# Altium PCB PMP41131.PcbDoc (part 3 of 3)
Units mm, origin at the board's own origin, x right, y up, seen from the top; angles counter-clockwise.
Board outline 53.98 x 39 mm, 6 copper layers (Top Layer, Signal Layer 1, Signal Layer 2, Signal Layer 3, Signal Layer 4, Bottom Layer), stack 1.835 mm thick; 91 components, 60 nets, 285 pads, 252 vias.
Unrouted connection lines stored in the file: 18.
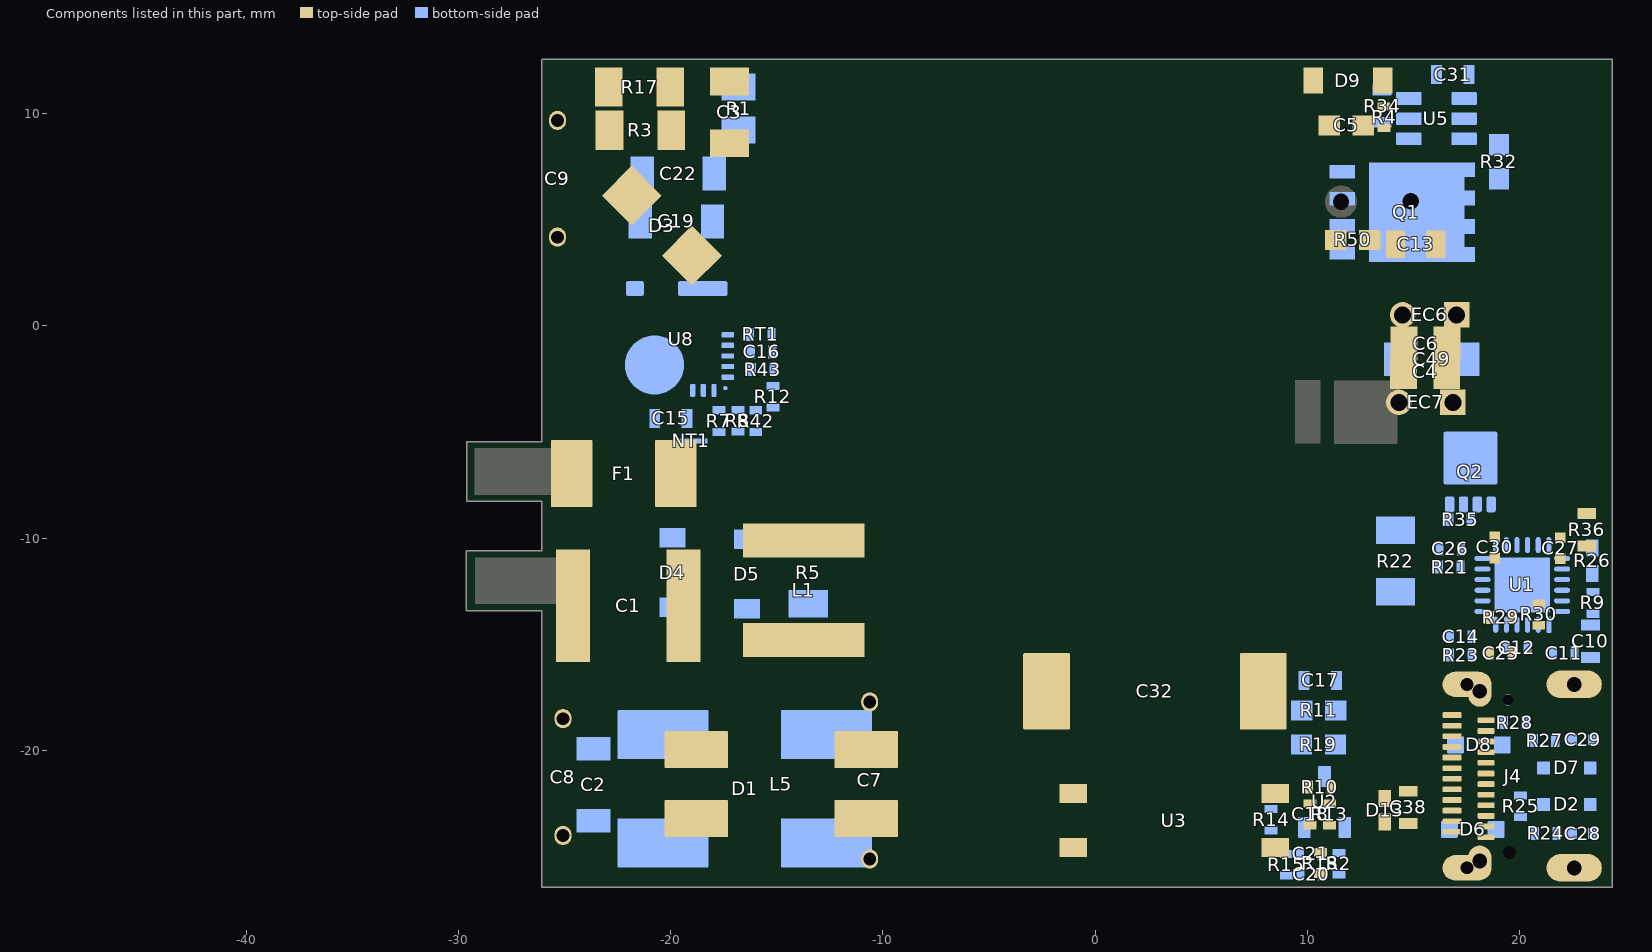
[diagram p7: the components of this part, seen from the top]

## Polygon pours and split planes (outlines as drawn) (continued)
RTN on Signal Layer 4 "SIGNAL_LAYER_4_RTN_P413" (solid, remove dead copper, pour order 413): 12.97,-25.62 13.806,-26.456 24.1,-26.456 24.1,-23.73 15.67,-23.73 15.34,-23.4 15.34,-22.91 12.97,-22.91
SGND on Signal Layer 4 "SIGNAL_LAYER_4_SGND_P412" (solid, remove dead copper, pour order 412): 13.419,2.71 13.419,-1.991 11.208,-1.991 11.232,-7.45 15.279,-7.45 15.279,2.71
VO_ACDC on Signal Layer 4 "SIGNAL_LAYER_4_VO_ACDC_P411" (solid, remove dead copper, pour order 411): 15.89,7.68 15.89,-7.48 23.922,-7.48 23.922,7.68
SGND on Signal Layer 4 "SIGNAL_LAYER_4_SGND_P385" (solid, remove dead copper, pour order 385): 17.39,-10.37 24.4,-10.37 24.4,-15.86 16.21,-15.86 16.21,-11.45 17.29,-10.37
Vbus on Signal Layer 4 "SIGNAL_LAYER_4_VBUS_P271" (solid, pour order 271): -15.13,7.14 -15.13,5.27 -13.82,3.96 -13.82,1.42 -12.27,1.42 -12.09,1.24 -12.09,-3.57 -11.84,-3.82 -10.01,-3.82 -9.97,-3.78 -10.31,-2.72 -10.57,-1.48 -10.7,0.12 -10.769,1.881 -11.409,2.521 -12.359,2.521 -12.78,2.942 -12.78,7.14
Vbus on Signal Layer 4 "SIGNAL_LAYER_4_VBUS_P371" (solid, remove dead copper, pour order 371): -12.48,3.97 -12.48,3.147 -12.23,2.847 -11.216,2.856 -10.505,2.145 -10.499,1.179 -10.35,-0.345 -8.805,-0.345 -5.175,-0.345 -4.26,2.923 -10.06,3.97
VSR_SW on Signal Layer 4 "SIGNAL_LAYER_4_VSR_SW_P376" (solid, remove dead copper, pour order 376): 11.04,2.57 11.04,2.01 11.19,1.86 11.19,-1.47 11.34,-1.62 12.16,-1.62 12.57,-1.21 12.64,-0.86 12.64,2.21 12.23,2.62 11.09,2.62
PGND on Signal Layer 4 "SIGNAL_LAYER_4_PGND_P273" (solid, remove dead copper, pour order 273): -25.83,12.25 -24.32,12.249 -24.32,3.41 -15.42,3.41 -15.361,-3.77 -25.83,-3.77
Vbus on Signal Layer 4 "SIGNAL_LAYER_4_VBUS_P366" (solid, remove dead copper, pour order 366): -9.636,5.496 -6.206,8.926 -6.105,8.926 -2.367,5.667 -4.79,3.4 -9.773,4.29 -12.47,4.29 -12.47,5.496
NetC2_1 on Signal Layer 4 "SIGNAL_LAYER_4_NETC2_1_P365" (solid, remove dead copper, pour order 365): -25.7,-23.21 -24.59,-23.21 -15.07,-13.69 -15.07,-12.31 -12.02,-12.31 -12.02,-14.12 -22.58,-24.68 -22.58,-25.37 -22.73,-25.52 -25.4,-25.52 -25.71,-25.21 -25.71,-23.26
Vbus on Signal Layer 4 "SIGNAL_LAYER_4_VBUS_P343" (solid, remove dead copper, pour order 343): -25.86,4.79 -25.05,4.79 -24.77,4.51 -24.77,-5.53 -21.03,-9.27 -12.25,-9.27 -12.25,-10.93 -22.5,-10.93 -25.86,-7.57
NetC2_1 on Signal Layer 4 "SIGNAL_LAYER_4_NETC2_1_P342" (solid, remove dead copper, pour order 342): -25.66,-23.4 -24.76,-23.4 -24.33,-22.97 -22.12,-22.97 -21.98,-23.11 -21.98,-24.68 -22.75,-25.45 -25.5,-25.45 -25.66,-25.29
Vbus on Signal Layer 4 "SIGNAL_LAYER_4_VBUS_P285" (solid, remove dead copper, pour order 285): -18.46,6.94 -18.46,5.62 -18.11,5.27 -15.01,5.27 -15.01,7.14 -18.26,7.14
SGND on Signal Layer 4 "SIGNAL_LAYER_4_SGND_P310" (solid, remove dead copper, pour order 310): 13.4,3.67 13.4,-4.72 22.52,-4.72 22.52,3.67
NetC7_2 on Signal Layer 4 "SIGNAL_LAYER_4_NETC7_2_P298" (solid, remove dead copper, pour order 298): -12.861,-22.266 -12.861,-25.246 -12.271,-25.836 -4.756,-25.836 -4.12,-25.2 -4.12,-23.1 -4.994,-22.226 -12.811,-22.226
NetC7_1 on Signal Layer 4 "SIGNAL_LAYER_4_NETC7_1_P293" (solid, remove dead copper, pour order 293): -12.785,-17.228 -12.785,-20.208 -12.195,-20.798 -5.095,-20.798 -4.49,-20.193 -4.49,-18.152 -5.455,-17.188 -12.735,-17.188
PGND on Signal Layer 4 "SIGNAL_LAYER_4_PGND_P286" (solid, remove dead copper, pour order 286): -25.76,12.35 -25.76,-7.7 -13.89,-7.7 -13.89,12.49 -25.68,12.49 -25.68,12.35
PGND on Top Layer "TOP_LAYER_PGND_P441" (solid, remove dead copper, pour order 441): -3.387,-19.037 -3.305,-19.119 -0.656,-19.119 -0.656,-17.01 -0.656,-15.394 -3.387,-15.394
Vbus on Top Layer "TOP_LAYER_VBUS_P440" (solid, remove dead copper, pour order 440): -16.61,-9.243 -16.61,-11.34 -10.81,-11.34 -10.81,-9.43 -10.997,-9.243 -16.496,-9.243
VO_ACDC on Top Layer "TOP_LAYER_VO_ACDC_P435" (solid, pour order 435): 19.9,12.43 19.9,7.47 23.89,7.47 23.89,12.43
VSR_SW on Top Layer "TOP_LAYER_VSR_SW_P428" (solid, remove dead copper, pour order 428): 14.18,12.31 19.21,12.31 19.21,9.67 17.345,9.677 17.324,8.431 14.18,8.448
VSR_SW on Top Layer "TOP_LAYER_VSR_SW_P426" (solid, remove dead copper, pour order 426): 10.52,9.82 10.52,10.31 10.66,10.45 11.32,10.45 11.52,10.25 11.52,9.82
PGND on Top Layer "TOP_LAYER_PGND_P422" (solid, remove dead copper, pour order 422): -25.83,12.25 -24.32,12.249 -24.32,3.41 -15.42,3.41 -15.361,-3.77 -25.83,-3.77
SGND on Top Layer "TOP_LAYER_SGND_P418" (solid, remove dead copper, pour order 418): 6.807,-19.02 6.986,-19.199 8.829,-19.199 9.029,-18.999 9.029,-15.417 6.807,-15.417
NetC2_1 on Top Layer "TOP_LAYER_NETC2_1_P389" (solid, remove dead copper, pour order 389): -16.58,-12.31 -16.58,-15.57 -16.57,-15.58 -10.89,-15.58 -10.89,-12.69 -11.27,-12.31 -16.54,-12.31
RTN on Top Layer "TOP_LAYER_RTN_P388" (solid, remove dead copper, pour order 388): 16.2,-16.04 24.07,-16.04 24.1,-16.01 24.1,-24.27 19.67,-24.27 19.67,-18.98 19.41,-18.72 16.47,-18.72 16.15,-18.4 16.15,-16.08
VO_ACDC on Top Layer "TOP_LAYER_VO_ACDC_P387" (solid, remove dead copper, pour order 387): 13.93,7.7 13.93,3.46 14.22,3.17 16.12,3.17 16.12,7.7
SGND on Top Layer "TOP_LAYER_SGND_P384" (solid, remove dead copper, pour order 384): 17.36,-10.39 24.35,-10.39 24.35,-15.88 16.18,-15.88 16.18,-11.47 17.26,-10.39
NetC7_2 on Top Layer "TOP_LAYER_NETC7_2_P383" (solid, remove dead copper, pour order 383): -13.476,-22.308 -13.476,-25.912 -5.672,-25.912 -5.672,-22.308
NetC7_1 on Top Layer "TOP_LAYER_NETC7_1_P382" (solid, remove dead copper, pour order 382): -13.432,-17.321 -13.432,-20.966 -5.748,-20.966 -5.748,-17.321
VOUT_C on Top Layer "TOP_LAYER_VOUT_C_P379" (solid, remove dead copper, pour order 379): 12.9,-22.7 19.58,-22.7 19.58,-19.16 19.27,-18.85 16.13,-18.85 15.8,-18.52 15.8,-10.55 16.93,-9.42 23.86,-9.42 23.86,-7.77 12.9,-7.77
RTN on Top Layer "TOP_LAYER_RTN_P377" (solid, remove dead copper, pour order 377): 12.93,-25.6 13.766,-26.436 24.06,-26.436 24.06,-23.71 15.63,-23.71 15.3,-23.38 15.3,-22.89 12.93,-22.89
SGND on Top Layer "TOP_LAYER_SGND_P362" (solid, remove dead copper, pour order 362): 13.379,2.73 13.379,-1.971 10.948,-1.971 10.972,-7.43 15.239,-7.43 15.239,2.73
VSR_SW on Top Layer "TOP_LAYER_VSR_SW_P351" (solid, remove dead copper, pour order 351): 4.82,-3.09 5.57,-1.94 10.76,-1.94 10.76,-6.03 8.3,-6.03 7.23,-7.1 6.15,-7.1 3.53,-4.48 4.575,-3.335
VSR_SW on Top Layer "TOP_LAYER_VSR_SW_P350" (solid, remove dead copper, pour order 350): 9.288,3.989 10.08,3 11.15,2.73 12.83,2.73 12.83,-1.74 5.34,-1.74 5.34,3.96 5.38,3.96
VSW on Top Layer "TOP_LAYER_VSW_P327" (solid, remove dead copper, pour order 327): -20.38,3.31 -19.84,2.77 -19.84,2.12 -19.67,1.95 -17.7,1.95 -17.46,2.19 -17.46,3.21 -18.98,4.73 -20.38,3.33
Vbus on Top Layer "TOP_LAYER_VBUS_P282" (solid, remove dead copper, pour order 282): -18.25,9.28 -18.25,7.05 -18.5,6.8 -18.5,5.55 -18.1,5.15 -16.64,5.15 -16.07,5.72 -16.07,9.08 -16.27,9.28 -18.27,9.28
VO_ACDC on Top Layer "TOP_LAYER_VO_ACDC_P253" (solid, remove dead copper, pour order 253): 15.85,7.7 15.85,-7.46 23.882,-7.46 23.882,7.7
VO_ACDC on Signal Layer 2 "SIGNAL_LAYER_2_VO_ACDC_P437" (solid, pour order 437): 19.9,12.43 19.9,7.19 23.94,7.19 23.94,12.43
RTN on Signal Layer 2 "SIGNAL_LAYER_2_RTN_P403" (solid, remove dead copper, pour order 403): 16.21,-16.05 24.08,-16.05 24.11,-16.02 24.11,-24.28 19.68,-24.28 19.68,-18.99 19.42,-18.73 16.48,-18.73 16.16,-18.41 16.16,-16.09
VO_ACDC on Signal Layer 2 "SIGNAL_LAYER_2_VO_ACDC_P402" (solid, remove dead copper, pour order 402): 13.94,7.32 13.94,3.45 14.23,3.16 16.13,3.16 16.13,7.32
SGND on Signal Layer 2 "SIGNAL_LAYER_2_SGND_P401" (solid, remove dead copper, pour order 401): 17.37,-10.4 24.36,-10.4 24.36,-15.89 16.19,-15.89 16.19,-11.48 17.27,-10.4
VOUT_C on Signal Layer 2 "SIGNAL_LAYER_2_VOUT_C_P400" (solid, remove dead copper, pour order 400): 12.91,-22.71 19.59,-22.71 19.59,-19.17 19.28,-18.86 16.14,-18.86 15.81,-18.53 15.81,-10.56 16.94,-9.43 23.87,-9.43 23.87,-7.78 12.91,-7.78
RTN on Signal Layer 2 "SIGNAL_LAYER_2_RTN_P399" (solid, remove dead copper, pour order 399): 12.94,-25.61 13.776,-26.446 24.07,-26.446 24.07,-23.72 15.64,-23.72 15.31,-23.39 15.31,-22.9 12.94,-22.9
SGND on Signal Layer 2 "SIGNAL_LAYER_2_SGND_P398" (solid, remove dead copper, pour order 398): 13.389,2.72 13.389,-1.981 10.971,-1.981 10.994,-7.44 15.249,-7.44 15.249,2.72
VO_ACDC on Signal Layer 2 "SIGNAL_LAYER_2_VO_ACDC_P397" (solid, remove dead copper, pour order 397): 15.86,7.3 15.86,-7.47 24.03,-7.47 24.03,7.3
VSR_SW on Signal Layer 2 "SIGNAL_LAYER_2_VSR_SW_P370" (solid, remove dead copper, pour order 370): 11.08,2.57 11.08,1.97 11.21,1.84 11.21,-1.49 11.42,-1.7 11.42,-1.72 12.35,-1.72 12.59,-1.48 12.59,-1.23 12.68,-1.14 12.68,2.25 12.33,2.6 11.11,2.6
Vbus on Signal Layer 2 "SIGNAL_LAYER_2_VBUS_P296" (solid, remove dead copper, pour order 296): -14.439,-9.27 -14.439,-10.63 -13.909,-11.16 -12.889,-11.16 -12.499,-10.77 -12.499,-9.53 -12.769,-9.26 -12.779,-9.27
NetC2_1 on Signal Layer 2 "SIGNAL_LAYER_2_NETC2_1_P269" (solid, remove dead copper, pour order 269): -14.35,-12.3 -14.35,-13.66 -13.82,-14.19 -12.8,-14.19 -12.41,-13.8 -12.41,-12.56 -12.68,-12.29 -12.69,-12.3
PGND on Signal Layer 2 "SIGNAL_LAYER_2_PGND_P359" (solid, remove dead copper, pour order 359): -3.04,-16.6 -3.04,-17.52 -1.45,-19.11 -0.76,-19.11 -0.66,-19.01 -0.66,-16.81 -0.87,-16.6
PGND on Signal Layer 2 "SIGNAL_LAYER_2_PGND_P312" (solid, remove dead copper, pour order 312): -25.68,12.28 -25.68,-19.34 -13.94,-19.34 -13.94,12.42 -25.6,12.42 -25.6,12.28
VO_ACDC on Signal Layer 1 "SIGNAL_LAYER_1_VO_ACDC_P436" (solid, pour order 436): 19.9,12.42 19.9,7.46 23.94,7.46 23.94,12.42
VSR_SW on Signal Layer 1 "SIGNAL_LAYER_1_VSR_SW_P430" (solid, remove dead copper, pour order 430): 14.18,12.29 19.21,12.29 19.21,9.65 17.345,9.657 17.326,8.551 14.18,8.568
RTN on Signal Layer 1 "SIGNAL_LAYER_1_RTN_P396" (solid, remove dead copper, pour order 396): 16.2,-16.04 24.07,-16.04 24.1,-16.01 24.1,-24.27 19.67,-24.27 19.67,-18.98 19.41,-18.72 16.47,-18.72 16.15,-18.4 16.15,-16.08
VO_ACDC on Signal Layer 1 "SIGNAL_LAYER_1_VO_ACDC_P395" (solid, remove dead copper, pour order 395): 13.93,7.7 13.93,3.46 14.22,3.17 16.12,3.17 16.12,7.7
SGND on Signal Layer 1 "SIGNAL_LAYER_1_SGND_P394" (solid, remove dead copper, pour order 394): 17.36,-10.39 24.35,-10.39 24.35,-15.88 16.18,-15.88 16.18,-11.47 17.26,-10.39
VOUT_C on Signal Layer 1 "SIGNAL_LAYER_1_VOUT_C_P393" (solid, remove dead copper, pour order 393): 12.9,-22.7 19.58,-22.7 19.58,-19.16 19.27,-18.85 16.13,-18.85 15.8,-18.52 15.8,-10.55 16.93,-9.42 23.86,-9.42 23.86,-7.77 12.9,-7.77
RTN on Signal Layer 1 "SIGNAL_LAYER_1_RTN_P392" (solid, remove dead copper, pour order 392): 12.93,-25.6 13.766,-26.436 24.06,-26.436 24.06,-23.71 15.63,-23.71 15.3,-23.38 15.3,-22.89 12.93,-22.89
SGND on Signal Layer 1 "SIGNAL_LAYER_1_SGND_P391" (solid, remove dead copper, pour order 391): 13.379,2.73 13.379,-1.971 11.198,-1.971 11.221,-7.43 15.239,-7.43 15.239,2.73
VO_ACDC on Signal Layer 1 "SIGNAL_LAYER_1_VO_ACDC_P390" (solid, remove dead copper, pour order 390): 15.85,7.7 15.85,-7.46 23.882,-7.46 23.882,7.7
Vbus on Signal Layer 1 "SIGNAL_LAYER_1_VBUS_P276" (solid, pour order 276): -16.88,5.36 -16.88,2.06 -13.75,2.06 -13.772,1.312 -12.64,1.312 -12.085,0.638 -12.085,-3.79 -10.93,-3.79 -9.94,-3.79 -10.16,-3.14 -10.46,-2 -10.65,-0.61 -10.67,0.71 -10.682,1.49 -10.67,2.8 -12.284,2.8 -12.7,3.216 -12.7,5.36
Vbus on Signal Layer 1 "SIGNAL_LAYER_1_VBUS_P372" (solid, remove dead copper, pour order 372): -12.443,4.14 -10.819,4.136 -10.36,3.61 -10.36,-0.621 -2.873,-0.621 -3.48,3.63 -10.111,5.25 -12.443,5.25
PGND on Signal Layer 1 "SIGNAL_LAYER_1_PGND_P290" (solid, remove dead copper, pour order 290): -25.82,12.1 -25.82,-7.29 -13.87,-7.29 -13.87,12.24 -25.74,12.24 -25.74,12.1
VSR_SW on Signal Layer 1 "SIGNAL_LAYER_1_VSR_SW_P375" (solid, remove dead copper, pour order 375): 11.07,2.56 11.07,1.96 11.2,1.83 11.2,-1.5 11.41,-1.71 11.41,-1.73 12.34,-1.73 12.6,-1.47 12.6,-1.22 12.67,-1.15 12.67,2.24 12.25,2.66 11.17,2.66
NetC7_2 on Signal Layer 1 "SIGNAL_LAYER_1_NETC7_2_P284" (solid, remove dead copper, pour order 284): -12.3,-22.48 -12.56,-22.74 -12.56,-25.51 -4.81,-25.51 -4.63,-25.33 -4.63,-22.94 -5.09,-22.48
NetC7_1 on Signal Layer 1 "SIGNAL_LAYER_1_NETC7_1_P287" (solid, remove dead copper, pour order 287): -12.37,-17.939 -12.51,-18.079 -12.51,-20.99 -4.901,-20.99 -4.58,-20.669 -4.58,-18.589 -5.23,-17.939
NetC2_1 on Signal Layer 1 "SIGNAL_LAYER_1_NETC2_1_P369" (solid, remove dead copper, pour order 369): -16.57,-12.3 -11.49,-12.3 -10.92,-12.87 -10.92,-15.48 -16.57,-15.48
Vbus on Signal Layer 1 "SIGNAL_LAYER_1_VBUS_P373" (solid, remove dead copper, pour order 373): -15.106,7.34 -9.417,7.32 -2.254,10.377 -2.254,5.277 -3.2,3.86 -9.856,5.5 -12.53,5.5 -13.07,4.96 -15.106,4.96
NetC2_1 on Signal Layer 1 "SIGNAL_LAYER_1_NETC2_1_P363" (solid, remove dead copper, pour order 363): -25.72,-23.22 -24.61,-23.22 -14.98,-13.59 -14.94,-13.59 -14.94,-12.66 -14.97,-12.63 -12.4,-12.63 -12.04,-12.99 -12.04,-14.13 -22.6,-24.69 -22.6,-25.38 -22.75,-25.53 -25.42,-25.53 -25.73,-25.22 -25.73,-23.27
Vbus on Signal Layer 1 "SIGNAL_LAYER_1_VBUS_P364" (solid, remove dead copper, pour order 364): -12.83,-9.26 -12.48,-9.61 -12.48,-10.73 -12.77,-11.02 -20.49,-11.02 -25.87,-5.64 -25.87,7.2 -25.77,7.3 -25.76,7.29 -24.28,7.29 -24.28,3.98 -24.64,3.62 -24.64,-4.2 -19.58,-9.26
NetC2_1 on Signal Layer 1 "SIGNAL_LAYER_1_NETC2_1_P357" (solid, remove dead copper, pour order 357): -14.99,-12.28 -12.76,-12.28 -12.11,-12.93 -12.11,-14.08 -12.3,-14.27 -14.33,-14.27 -14.99,-13.61
NetC2_1 on Signal Layer 1 "SIGNAL_LAYER_1_NETC2_1_P341" (solid, remove dead copper, pour order 341): -25.68,-23.21 -24.57,-23.21 -24.01,-22.65 -22.64,-22.65 -22.6,-22.61 -22.6,-25.22 -22.89,-25.51 -25.42,-25.51 -25.69,-25.24 -25.69,-23.22
NetC7_2 on Signal Layer 1 "SIGNAL_LAYER_1_NETC7_2_P300" (solid, remove dead copper, pour order 300): -12.97,-22.758 -12.97,-25.677 -12.471,-26.176 -4.956,-26.176 -4.53,-25.75 -4.53,-23.23 -5.27,-22.49 -12.635,-22.49
NetC7_1 on Signal Layer 1 "SIGNAL_LAYER_1_NETC7_1_P295" (solid, remove dead copper, pour order 295): -12.985,-17.716 -12.985,-20.548 -12.395,-21.138 -5.295,-21.138 -4.69,-20.533 -4.69,-18.492 -5.655,-17.528 -12.749,-17.528
Vbus on Signal Layer 1 "SIGNAL_LAYER_1_VBUS_P288" (solid, remove dead copper, pour order 288): -25.35,7.34 -15.08,7.34 -15.05,7.31 -15.05,5.04 -23.29,5.04 -24.65,3.68 -24.65,2.83 -25.72,2.83 -26.06,3.17 -26.06,7.3

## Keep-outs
Keep-Out Layer:
  text ".Layer_Name" at -61.462,-177.942 h1.52

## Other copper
Top Layer:
  rectangle net Neture: -26.79,-13.11 -24.34,-10.91
  region net LINE: -27.91,-5.78 -27.91,-7.96 -24.49,-7.96 -24.49,-5.78
  pour cut-out: -20.17,1.99 -20.16,1.98 -20.16,1.02 -15.41,1.02 -15.41,1.92 -20.11,1.92 -20.12,1.93
  text ".Layer_Name" at -61.462,-177.942 h1.52
Signal Layer 1:
  rectangle net PGND: -1.54,-18.96 -0.82,-16.79
Signal Layer 2:
  rectangle net NetC7_1: -11.2,-20.65 -6.54,-18.76
  rectangle net NetC7_2: -11.23,-25.722 -6.11,-23.43
  pour cut-out: -15.36,-12.15 -15.36,-14.18 -15.02,-14.18 -15,-14.16 -15,-12.15
  region net Vbus: -18.153,6.99 -18.23,6.815 -18.19,5.82 -17.89,5.51 -16.34,5.51 -15.88,6.051 -15.88,6.99
Bottom Layer:
  rectangle net SGND: 7.67,-19.07 8.39,-16.92
  rectangle net PGND: -1.5,-18.95 -0.78,-16.8
  rectangle net NetC2_1: -14.42,-13.92 -12.2,-12.32
  rectangle net Vbus: -14.47,-10.93 -12.13,-9.39
  pour cut-out: -26.04,-3.7 -24.67,-3.7 -24.67,-14.11 -26.04,-14.11
  text ".Layer_Name" at -61.462,-177.942 h1.52

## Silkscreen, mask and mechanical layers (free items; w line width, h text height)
Top Overlay:
  circle w0.127: c0,0.02 r5.6
  lines w0.01: -13.645,-5.179 -13.549,1.125 -12.28,1.125 -12.28,-4.725 -8.86,-8.145 -8.86,-12.265 9.149,-12.265 9.149,-14.274 -9.789,-14.274 -10.138,-13.925 -10.138,-8.686 -13.645,-5.179 ; -13.59,7.95 -12.26,7.95 -12.26,12.59 -13.59,12.59 -13.59,7.95 ; -10.6,7.94 -8.29,7.94 -8.29,12.56 -10.6,12.56 -10.6,7.94
  lines w0.127: -9,-8 -9,-12.48 0,-12.48 9,-12.48 8.989,-8.333 ccw(c8.277,-8.326) 7.983,-7.679 7.507,-7.895 ; -9,-7.99 cw(c-8.199,-8.588) -7.597,-7.789 ; -9,8.59 -9,12.52 0,12.52 9,12.52 9,8.68 ; -8.99,8.57 ccw(c-8.014,8.787) -7.562,7.895 ; -7.616,-7.778 ccw(c0,0.02) 7.498,-7.891 ; -7.565,7.867 cw(c0,0.02) 7.503,7.927 ; 7.468,7.974 ccw(c8.018,8.808) 9.01,8.68
  text ".Layer_Name" at -61.462,-177.942 h1.52
Bottom Overlay:
  text ".Layer_Name" at -61.462,-177.942 h1.52
Top Paste:
  text ".Layer_Name" at -61.462,-177.942 h1.52
Bottom Paste:
  text ".Layer_Name" at -61.462,-177.942 h1.52
Top Solder:
  rectangle: 13.52,-5.63 15.18,2.65
  rectangle: 15.91,-5.61 18.71,2.69
  rectangle: 13.2,-9.16 23.6,-8.01
  rectangle: 13.21,-20.86 15.42,-8.06
  region: -25.38,-0.02 -25.38,-2.96 -17.39,-2.96 -17.39,-0.02
  text ".Layer_Name" at -61.462,-177.942 h1.52
  text ".Layer_Name" at -61.462,-177.942 h1.52
Bottom Solder:
  region: 13.18,-25.18 15.3,-25.18 15.3,-13.42 13.18,-13.42
  region: -24.143,11.93 -24.143,6.31 -20.39,6.31 -20.39,11.93
  region: 19.46,-7.35 19.46,7.62 16.07,7.62 16.07,-7.35
  region: -25.5,0.17 -25.5,-3.39 -21.97,-3.39 -21.97,0.17
  region: -24.31,-2.87 -24.31,-8.26 -21.16,-8.26 -21.16,-2.87
  region: -24.19,-8.257 -19.63,-8.257 -19.63,-5.45 -24.19,-5.45
  region: 13.36,-8.64 15.29,-8.64 15.29,2.36 13.36,2.36
  lines w0.4: -24.43,-0.1 -24.43,2.05 ; -24.41,2.14 -23.09,4.21 ; -23.93,0.09 -23.93,1.86 ; -23.92,1.91 -22.6,3.98
  text ".Layer_Name" at -61.462,-177.942 h1.52
Drill Guide:
  text ".Layer_Name" at -61.462,-177.942 h1.52
M1 Board Outline:
  circle w0.127: c0,0 r5.6
  lines w0.01: -13.645,-5.199 -10.138,-8.706 -10.138,-13.945 -9.789,-14.294 9.149,-14.294 9.149,-12.285 -8.86,-12.285 -8.86,-8.165 -12.28,-4.745 -12.28,1.105 -13.549,1.105 -13.645,-5.199 ; -13.59,7.93 -13.59,12.57 -12.26,12.57 -12.26,7.93 -13.59,7.93 ; -10.6,7.92 -8.29,7.92 -8.29,12.54 -10.6,12.54 -10.6,7.92
  lines w0.127: -26.09,-13.41 -29.63,-13.41 -29.63,-10.6 -26.08,-10.6 ; -26.07,-8.26 -29.61,-8.26 -29.61,-5.45 -26.06,-5.45 -26.06,12.543 ; -26.06,-26.45 24.35,-26.45 24.35,12.554 -26.04,12.554 ; -26.06,-26.436 -26.06,-13.41 ; -26.06,-10.59 -26.06,-8.26 ; -9,-8.02 -9,-12.5 0,-12.5 9,-12.5 8.99,-8.91 ; -9,-8.01 cw(c-8.199,-8.608) -7.597,-7.809 ; -9,8.57 -9,12.5 0,12.5 9,12.5 9,8.66 ; -8.99,8.55 ccw(c-8.014,8.767) -7.562,7.875 ; -7.616,-7.798 ccw(c0,0) 7.498,-7.911 ; -7.565,7.847 cw(c0,0) 7.503,7.907 ; 7.468,7.954 ccw(c8.018,8.788) 9.01,8.66 ; 7.507,-7.915 cw(c7.942,-8.869) 8.99,-8.88
  text ".Layer_Name" at -61.462,-177.942 h1.52
M2 Board Dimensions:
  rectangle: -76.118,-163.121 -72.943,-159.946
  rectangle: -72.943,-166.296 -63.418,-163.121
  lines w0.178: -76.118,-163.121 -50.718,-163.121 ; -72.943,-166.296 -72.943,-159.946 ; -69.768,-166.296 -69.768,-159.946 ; -63.418,-166.296 -63.418,-159.946 ; -57.068,-166.296 -57.068,-159.946 ; -76.118,-166.296 -50.718,-166.296 -50.718,-159.946 -76.118,-159.946 -76.118,-166.296
  text ".Layer_Name" at -61.462,-177.942 h1.52
M3 3D STEP Top:
  text ".Layer_Name" at -61.462,-177.942 h1.52
M4 3D STEP Bottom:
  text ".Layer_Name" at -61.462,-177.942 h1.52
M5 Assembly Top:
  lines w0.254: -83.535,-179.762 84.105,-179.762 ; -83.535,-174.597 84.156,-174.597 ; -83.535,-169.433 -83.535,-184.927 18.192,-184.927 84.156,-184.927 84.156,-169.433 -83.522,-169.433 -83.522,-184.927 -43.504,-184.927 ; -20.924,-184.927 -20.924,-169.433 ; 11.258,-174.597 11.258,-169.433 ; 32.594,-174.597 32.594,-169.433 ; 48.393,-185.092 48.393,-179.94
  text "COMPONENTS MARKED 'DNP' SHOULD NOT BE POPULATED." at -46.819,-164.226 h1.52
  text "ASSEMBLY VARIANT:" at -46.832,-167.159 h1.52
  text ".VariantName" at -20.517,-167.159 h1.52
  text "PCB VIEWED FROM TOP SIDE" at -81.922,-172.79 h1.52
  text "BOARD #:" at -19.019,-172.79 h1.52
  text ".PRJ_Number" at -5.163,-172.79 h1.52
  text "REV:" at 16.287,-172.79 h1.52
  text ".PCB_Rev" at 23.691,-172.79 h1.52
  text "SVN REV:" at 37.572,-172.79 h1.52
  text ".VersionControl_RevNumber" at 50.425,-172.79 h1.52
  text "TID #:" at -19.019,-177.954 h1.52
  text ".TID" at -5.163,-177.954 h1.52
  text "PLOT NAME =" at -81.922,-183.17 h1.52
  text ".plot_File_Name" at -61.462,-183.17 h1.52
  text "GENERATED    :" at -18.968,-183.17 h1.52
  text ".Print_Date" at 3.117,-183.17 h1.52
  text ".Print_Time" at 21.634,-183.17 h1.52
  text "TEXAS INSTRUMENTS" at 53.752,-183.17 h1.52
M6 Assembly Bottom:
  lines w0.254: -83.547,-174.61 84.143,-174.61 ; -83.497,-179.775 84.143,-179.775 ; -47.784,-185.105 -47.784,-179.953 ; -31.985,-174.61 -31.985,-169.445 ; -10.649,-174.61 -10.649,-169.445 ; 21.532,-184.939 21.532,-169.445 ; 44.113,-184.939 84.131,-184.939 84.131,-169.445 -83.547,-169.445 -83.547,-184.939 -17.584,-184.939 84.143,-184.939 84.143,-169.445
  text "COMPONENTS MARKED 'DNP' SHOULD NOT BE POPULATED." at 78.873,-164.213 h1.52
  text ".VariantName" at 52.355,-167.159 h1.52
  text "ASSEMBLY VARIANT:" at 78.746,-167.159 h1.52
  text ".VersionControl_RevNumber" at -49.816,-172.803 h1.52
  text "SVN REV:" at -36.964,-172.803 h1.52
  text ".PCB_Rev" at -23.083,-172.803 h1.52
  text "REV:" at -15.679,-172.803 h1.52
  text ".PRJ_Number" at 5.772,-172.803 h1.52
  text "BOARD #:" at 19.627,-172.803 h1.52
  text "PCB VIEWED FROM BOTTOM SIDE" at 82.53,-172.803 h1.52
  text ".TID" at 5.772,-177.967 h1.52
  text "TID #:" at 19.627,-177.967 h1.52
  text "TEXAS INSTRUMENTS" at -53.144,-183.183 h1.52
  text ".Print_Time" at -21.025,-183.183 h1.52
  text ".Print_Date" at -2.509,-183.183 h1.52
  text "GENERATED    :" at 19.577,-183.183 h1.52
  text ".plot_File_Name" at 62.071,-183.183 h1.52
  text "PLOT NAME =" at 82.53,-183.183 h1.52
M9 Title Sheet:
  drawing of 57 lines, arcs and shapes, not listed
  text "1" at -57.326,47.991 h1.78
  text "2" at 6.064,47.991 h1.78
  text "3" at 69.293,47.991 h1.78
  text "4" at 132.962,47.991 h1.78
  text "5" at 196.437,47.991 h1.78
  text "6" at 260.064,47.991 h1.78
  text "A" at -86.697,18.959 h1.78
  text "A" at 289.223,18.959 h1.78
  text "B" at -86.697,-41.493 h1.78
  text "B" at 289.223,-41.493 h1.78
  text "C" at -86.697,-101.818 h1.78
  text "C" at 289.223,-101.818 h1.78
  text "PROJECT TITLE:" at 212.007,-149.087 h1.14
  text ".PRJ_Title" at 213.277,-152.474 h1.78
  text "DESIGNED FOR:" at 212.007,-156.733 h1.14
  text ".PRJ_Customer" at 213.277,-160.289 h1.78
  text "D" at -86.697,-162.016 h1.78
  text "D" at 289.223,-162.016 h1.78
  text "FILE NAME:" at 212.007,-164.353 h1.14
  text ".PCB_File_Name_No_Path" at 213.277,-167.401 h1.78
  text "Texas Instruments (TI) and/or its licensors do not warrant the accuracy or completeness of this specification" at 85.782,-171.511 h1.14
  text "ENGINEER:" at 212.007,-171.719 h1.14
  text "LAYOUT BY:" at 250.234,-171.719 h1.14
  text "or any information contained therein. TI and/or its licensors do not warrant that this design will meet" at 84.639,-174.373 h1.14
  text ".PRJ_Engineer" at 213.277,-175.656 h1.78
  text ".PCB_Layout" at 251.517,-175.656 h1.78
  text "the specifications, will be suitable for your application or fit for any particular purpose, or will operate in" at 84.639,-177.235 h1.14
  text ".Layer_Name" at -61.462,-177.942 h1.52
  text "ALTIUM DESIGNER VERSION:" at 250.234,-179.593 h1.14
  text "an implementation. TI and/or its licensors do not warrant that the design is production worthy. You should" at 84.639,-180.097 h1.14
  text "completely validate and test your design implementation to confirm the system functionality for your application." at 85.782,-182.958 h1.14
  text ".print_Scale" at 213.277,-182.979 h1.78
  text ".Application_BuildNumber" at 251.517,-182.979 h1.78
  text "1" at -57.326,-188.229 h1.78
  text "2" at 6.064,-188.229 h1.78
  text "3" at 69.293,-188.229 h1.78
  text "4" at 132.962,-188.229 h1.78
  text "5" at 196.437,-188.229 h1.78
  text "6" at 260.064,-188.229 h1.78
M10 Fab Notes:
  drawing of 189 lines, arcs and shapes, not listed
  text "DESIGN INFORMATION" at 238.385,5.311 h1.52
  text "MIN. TRACK WIDTH:" at 222.013,1.955 h1.52
  text "8" at 249.858,1.955 h1.52
  text "MIL" at 253.789,1.955 h1.52
  text "7.874" at 245.632,-1.136 h1.52
  text "MIN. CLEARANCE:" at 222.013,-1.198 h1.52
  text "MIL" at 253.789,-1.198 h1.52
  text "MIN. VIA PAD SIZE:" at 222.013,-4.351 h1.52
  text "24" at 249.096,-4.351 h1.52
  text "MIL" at 253.789,-4.351 h1.52
  text "0.05mm (2MIL)" at 239.666,-7.65 h1.52
  text "MINIMUM ANNULAR RING" at 213.651,-7.859 h1.52
  text "EXTERNAL" at 257.65,-7.859 h1.52
  text "PER" at 218.731,-10.656 h1.52
  text "IPC-D-275 CLASS 2 LEVEL C" at 224.319,-10.656 h1.52
  text "MIL, HOLES" at 262.12,-13.208 h1.52
  text "+/-" at 252.152,-13.426 h1.52
  text "+/-" at 273.843,-13.426 h1.52
  text "REGISTRATION TOLERANCES:" at 213.651,-13.453 h1.52
  text "METAL" at 244.125,-13.453 h1.52
  text "5" at 258.761,-13.453 h1.52
  text "3" at 279.919,-13.453 h1.52
  text "MIL" at 282.872,-13.453 h1.52
  text "HOLE SIZE TOLERANCE (UNLESS OTHERWISE SPECIFIED):" at 213.651,-15.951 h1.52
  text "+/-" at 273.843,-16.024 h1.52
  text "3" at 279.919,-16.051 h1.52
  text "MIL" at 282.872,-16.051 h1.52
  text "MATERIAL:" at 211.752,-19.547 h1.52
  text "FR-4 High Tg" at 236.808,-22.811 h1.52
  text "X" at 233.139,-23.014 h1.52
  text "FR-4" at 222.445,-23.129 h1.52
  text "OTHER" at 260.24,-23.129 h1.52
  text "62 MIL (1.6mm) +/-10%" at 230.576,-26.762 h1.52
  text "X" at 227.525,-26.824 h1.52
  text "THICKNESS:" at 213.651,-26.971 h1.52
  text "OTHER" at 263.212,-26.971 h1.52
  text "TOLERANCE:" at 213.651,-30.484 h1.52
  text "X" at 235.196,-30.484 h1.52
  text "ANSI IPC-6012 TYPE 3 CLASS 2" at 239.718,-30.484 h1.52
  text "OTHER +/-" at 239.717,-34.146 h1.52
  text "BOW & TWIST:" at 213.651,-37.834 h1.52
  text "X" at 235.196,-37.834 h1.52
  text "ANSI IPC-6012 TYPE 3 CLASS 2" at 239.718,-37.834 h1.52
  text "OTHER +/-" at 239.717,-41.56 h1.52
  text "DRILLING:" at 211.752,-44.878 h1.52
  text "NC_DRILL FILES" at 256.481,-47.55 h1.52
  text "REFERENCE:" at 213.651,-47.65 h1.52
  text "X" at 230.345,-47.652 h1.52
  text "AS SHOWN" at 234.866,-47.65 h1.52
  text "X" at 253.23,-47.65 h1.52
  text "OTHER" at 264.05,-51.263 h1.52
  text "PTH COPPER THICKNESS:" at 213.643,-51.353 h1.52
  text "X" at 242.579,-51.353 h1.52
  text "20-30 um" at 245.83,-51.353 h1.52
  text "BOARD FINISH:" at 211.752,-55.102 h1.52
  text "SILKSCREEN:" at 215.695,-57.899 h1.52
  text "X" at 240.022,-57.899 h1.52
  text "TOP" at 242.994,-57.899 h1.52
  text "X" at 252.976,-57.899 h1.52
  text "BOTTOM" at 255.973,-57.899 h1.52
  text "SILKSCREEN COLOR:" at 215.695,-61.841 h1.52
  text "X" at 239.997,-61.841 h1.52
  text "WHITE" at 242.994,-61.841 h1.52
  text "OTHER" at 255.973,-61.841 h1.52
  text "X" at 243.324,-65.484 h1.52
  text "GREEN" at 246.321,-65.484 h1.52
  text "OTHER" at 262.018,-65.484 h1.52
  text "SOLDER RESIST COLOR:" at 215.695,-65.659 h1.52
  text "X" at 243.324,-69.402 h1.52
  text "MATTE" at 246.321,-69.402 h1.52
  text "SEMI-GLOSS" at 262.007,-69.418 h1.52
  text "IMMERSION GOLD (ENIG)" at 238.701,-73.791 h1.52
  text "ENEPIG" at 272.675,-73.974 h1.52
  text "SURFACE FINISH:" at 211.752,-73.999 h1.52
  text "X" at 234.18,-73.999 h1.52
  text "IMM. TIN/SILVER OR EQUIV" at 220.122,-77.487 h1.52
  text "OTHER" at 256.481,-77.587 h1.52
  text "ARRAY/PANEL:" at 211.752,-81.534 h1.52
  text "CUT AND TRIM PER M1 BOARD OUTLINE" at 238.701,-81.743 h1.52
  text "N.C. ROUTE" at 238.701,-85.196 h1.52
  text "X" at 256.177,-85.196 h1.52
  text "V. SCORE" at 260.698,-85.196 h1.52
  text "CERTIFICATION:" at 211.752,-88.476 h1.52
  text "MATERIALS AND WORKMANSHIP FOR ALL PCBS" at 230.167,-88.476 h1.52
  text "TO MEET OR EXCEED THE REQUIREMENTS OF:" at 230.167,-90.865 h1.52
  text "X" at 220.96,-94.132 h1.52
  text "ANSI IPC-A-600F CLASS ->" at 224.211,-94.132 h1.52
  text "X" at 266.07,-94.132 h1.52
  text "2" at 268.864,-94.132 h1.52
  text "1" at 260.863,-94.17 h1.52
  text "3" at 277.855,-94.17 h1.52
  text "X" at 241.584,-97.884 h1.52
  text "RoHS" at 244.835,-97.884 h1.52
  text "OTHER" at 261.203,-97.884 h1.52
  text "PER ORDER" at 271.289,-97.884 h1.52
  text "ALL BOARDS MUST MEET OR EXCEED UL94-V0 REQUIREMENTS." at 212.451,-101.791 h1.52
  text "PCB MUST BEAR THE UL94V-0 UL REGISTERED MATERIAL ID NUMBER" at 212.451,-104.739 h1.52
  text "ADDITIONAL REQUIREMENTS:" at 211.752,-109.042 h1.52
  text "MICROSECTION:" at 213.651,-111.763 h1.52
  text "YES" at 236.657,-111.763 h1.52
  text "REQUIRED" at 258.539,-115.429 h1.52
  text "BARE BOARD ELEC. TEST:" at 213.651,-115.502 h1.52
  text "NONE" at 246.817,-115.502 h1.52
  text "X" at 255.542,-115.502 h1.52
  text "PER ORDER" at 273.575,-115.502 h1.52
  text "XX MIL VIAS REQUIRE NON-CONDUCTIVE FILL AND PLANARIZE" at 217.922,-120.708 h1.5
  text "XX MIL VIAS REQUIRE CONDUCTIVE FILL AND PLANARIZE" at 218.125,-123.348 h1.52
  text "OUTER XX MIL TRACES REQUIRE 50 OHM SINGLE-ENDED IMPEDANCE" at 218.1,-127.498 h1.47
  text "LAYER 2 & 3 (INNER LAYERS) XX MIL WIDE, XX MIL SPACE / TRACES REQUIRE 100 OHM DIFFERENTIAL IMPEDANCE" at 217.897,-133.486 h1.52
  text ".Layer_Name" at -61.462,-177.942 h1.52
M11 Gerber Information:
  lines w0.254: -83.535,-179.762 84.105,-179.762 ; -83.535,-174.597 84.156,-174.597 ; -83.535,-169.433 -83.535,-184.927 18.192,-184.927 84.156,-184.927 84.156,-169.433 -83.522,-169.433 -83.522,-184.927 -43.504,-184.927 ; -20.924,-184.927 -20.924,-169.433 ; 11.258,-174.597 11.258,-169.433 ; 32.594,-174.597 32.594,-169.433 ; 48.393,-185.092 48.393,-179.94
  text "ALL ARTWORK VIEWED FROM TOP SIDE" at -81.922,-172.79 h1.52
  text "BOARD #:" at -19.019,-172.79 h1.52
  text ".PRJ_Number" at -5.163,-172.79 h1.52
  text "REV:" at 16.287,-172.79 h1.52
  text ".PCB_Rev" at 23.691,-172.79 h1.52
  text "SVN REV:" at 37.572,-172.79 h1.52
  text ".VersionControl_RevNumber" at 50.425,-172.79 h1.52
  text "LAYER NAME =" at -81.922,-177.942 h1.52
  text "TID #:" at -19.019,-177.954 h1.52
  text ".TID" at -5.163,-177.954 h1.52
  text "PLOT NAME =" at -81.922,-183.17 h1.52
  text ".plot_File_Name" at -61.462,-183.17 h1.52
  text "GENERATED    :" at -18.968,-183.17 h1.52
  text ".Print_Date" at 3.117,-183.17 h1.52
  text ".Print_Time" at 21.634,-183.17 h1.52
  text "TEXAS INSTRUMENTS" at 53.752,-183.17 h1.52
M12 Stackup:
  drawing of 399 lines, arcs and shapes, not listed
  text "Layer" at 70.803,-78.258 h1.52
  text "Name" at 81.215,-78.258 h1.52
  text "Material" at 105.084,-78.258 h1.52
  text "Thickness" at 126.922,-78.258 h1.52
  text "Constant" at 143.428,-78.258 h1.52
  text "Board Layer Stack" at 157.902,-78.258 h1.52
  text "Top Overlay" at 81.215,-81.306 h1.52
  text "Top Solder" at 81.215,-84.354 h1.52
  text "Solder Resist" at 105.084,-84.354 h1.52
  text "0.50mil" at 126.922,-84.354 h1.52
  text "3.5" at 143.428,-84.354 h1.52
  text "1" at 70.803,-87.402 h1.52
  text "Top Layer" at 81.215,-87.402 h1.52
  text "5.51mil" at 126.922,-87.402 h1.52
  text "Dielectric 1" at 81.215,-90.45 h1.52
  text "FR-4 High Tg" at 105.084,-90.45 h1.52
  text "7.00mil" at 126.922,-90.45 h1.52
  text "4.2" at 143.428,-90.45 h1.52
  text "2" at 70.803,-93.498 h1.52
  text "Signal Layer 1" at 81.215,-93.498 h1.52
  text "2.76mil" at 126.922,-93.498 h1.52
  text "Dielectric 2" at 81.215,-96.546 h1.52
  text "FR-4 High Tg" at 105.084,-96.546 h1.52
  text "14.00mil" at 126.922,-96.546 h1.52
  text "4.2" at 143.428,-96.546 h1.52
  text "3" at 70.803,-99.594 h1.52
  text "Signal Layer 2" at 81.215,-99.594 h1.52
  text "2.76mil" at 126.922,-99.594 h1.52
  text "Dielectric 4" at 81.215,-102.642 h1.52
  text "FR-4 High Tg" at 105.084,-102.642 h1.52
  text "8.20mil" at 126.922,-102.642 h1.52
  text "4.2" at 143.428,-102.642 h1.52
  text "4" at 70.803,-105.69 h1.52
  text "Signal Layer 3" at 81.215,-105.69 h1.52
  text "2.76mil" at 126.922,-105.69 h1.52
  text "Dielectric 5" at 81.215,-108.738 h1.52
  text "FR-4 High Tg" at 105.084,-108.738 h1.52
  text "14.00mil" at 126.922,-108.738 h1.52
  text "4.2" at 143.428,-108.738 h1.52
  text "5" at 70.803,-111.786 h1.52
  text "Signal Layer 4" at 81.215,-111.786 h1.52
  text "2.76mil" at 126.922,-111.786 h1.52
  text "Dielectric 3" at 81.215,-114.834 h1.52
  text "FR-4 High Tg" at 105.084,-114.834 h1.52
  text "7.00mil" at 126.922,-114.834 h1.52
  text "4.2" at 143.428,-114.834 h1.52
  text "6" at 70.803,-117.882 h1.52
  text "Bottom Layer" at 81.215,-117.882 h1.52
  text "5.51mil" at 126.922,-117.882 h1.52
  text "Bottom Solder" at 81.215,-120.93 h1.52
  text "Solder Resist" at 105.084,-120.93 h1.52
  text "0.50mil" at 126.922,-120.93 h1.52
  text "3.5" at 143.428,-120.93 h1.52
  text "Bottom Overlay" at 81.215,-123.978 h1.52
  text ".Layer_Name" at -61.462,-177.942 h1.52
M13 Component Bodies Top:
  text ".Layer_Name" at -61.462,-177.942 h1.52
M14 Component Bodies Bottom:
  text ".Layer_Name" at -61.462,-177.942 h1.52
M15 Courtyards Top:
  text ".Layer_Name" at -61.462,-177.942 h1.52
M16 Courtyards Bottom:
  text ".Layer_Name" at -61.462,-177.942 h1.52
Drill Drawing:
  circle w0.254: c79.523,14.097 r0.421
  circle w0.254: c79.523,14.097 r0.702
  circle w0.254: c79.523,-11.165 r0.702
  lines w0.254: 78.821,-30.462 79.172,-30.462 79.172,-30.813 79.873,-30.813 79.873,-30.462 80.224,-30.462 80.224,-29.76 79.873,-29.76 79.873,-29.409 79.172,-29.409 79.172,-29.76 78.821,-29.76 78.821,-30.462 ; 78.821,-24.146 79.172,-24.146 79.523,-24.497 79.873,-24.146 80.224,-24.146 79.873,-23.796 80.224,-23.445 79.873,-23.445 79.523,-23.094 79.172,-23.445 78.821,-23.445 79.172,-23.796 78.821,-24.146 ; 78.821,-21.34 79.523,-20.989 80.224,-21.34 79.873,-20.638 80.224,-19.936 79.523,-20.287 78.821,-19.936 79.172,-20.638 78.821,-21.34 ; 78.821,-17.831 79.172,-17.831 79.523,-18.182 79.873,-17.831 80.224,-17.831 79.873,-17.48 80.224,-17.129 79.873,-17.129 79.523,-16.778 79.172,-17.129 78.821,-17.129 79.172,-17.48 78.821,-17.831 ; 78.821,-15.024 79.523,-14.673 80.224,-15.024 79.873,-14.322 80.224,-13.621 79.523,-13.972 78.821,-13.621 79.172,-14.322 78.821,-15.024 ; 78.821,-4.849 79.523,-5.551 80.224,-4.849 79.523,-4.148 78.821,-4.849 ; 78.821,2.168 80.224,2.168 79.523,0.765 78.821,2.168 ; 78.821,3.922 78.821,4.273 79.172,4.624 78.821,4.975 78.821,5.326 79.172,5.326 79.523,4.975 79.873,5.326 80.224,5.326 80.224,4.975 79.873,4.624 80.224,4.273 80.224,3.922 79.873,3.922 79.523,4.273 79.172,3.922 78.821,3.922 ; 78.821,8.483 80.224,8.483 79.523,7.08 78.821,8.483 ; 78.821,10.238 80.224,10.238 80.224,11.641 78.821,11.641 78.821,10.238 ; 79.101,-21.059 79.523,-20.848 79.944,-21.059 79.733,-20.638 79.944,-20.217 79.523,-20.427 79.101,-20.217 79.312,-20.638 79.101,-21.059 ; 79.101,-17.691 79.312,-17.691 79.523,-17.901 79.733,-17.691 79.944,-17.691 79.733,-17.48 79.944,-17.27 79.733,-17.27 79.523,-17.059 79.312,-17.27 79.101,-17.27 79.312,-17.48 79.101,-17.691 ; 79.101,1.887 79.944,1.887 79.523,1.045 79.101,1.887 ; 79.101,10.518 79.944,10.518 79.944,11.36 79.101,11.36 79.101,10.518
  lines w0.305: 77.548,-31.76 162.754,-31.76 ; 77.548,15.606 162.754,15.606 ; 86.13,-34.918 86.13,18.764 ; 94.563,-34.918 94.563,18.764 ; 110.732,-34.918 110.732,18.764 ; 117.314,-34.918 117.314,18.764 ; 126.843,-34.918 126.843,18.764 ; 148.366,-34.918 148.366,18.764 ; 77.548,-34.918 162.754,-34.918 162.754,18.764 77.548,18.764 77.548,-34.918
  text "Symbol" at 79.443,16.553 h1.83
  text "Quantity" at 87.078,16.553 h1.83
  text "Finished Hole Size" at 95.51,16.553 h1.83
  text "Plated" at 111.679,16.553 h1.83
  text "Hole Type" at 118.261,16.553 h1.83
  text "Drill Layer Pair" at 127.79,16.553 h1.83
  text "Hole Tolerance" at 149.314,16.553 h1.83
  text "1" at 87.078,13.395 h1.52
  text "23.62mil (0.600mm)" at 95.51,13.395 h1.52
  text "NPTH" at 111.679,13.395 h1.52
  text "Round" at 118.261,13.395 h1.52
  text "Top Layer - Bottom Layer" at 127.79,13.395 h1.52
  text "+/-1.18mil" at 149.314,13.395 h1.52
  text "68" at 87.078,10.238 h1.52
  text "7.87mil (0.200mm)" at 95.51,10.238 h1.52
  text "PTH" at 111.679,10.238 h1.52
  text "Round" at 118.261,10.238 h1.52
  text "Top Layer - Bottom Layer" at 127.79,10.238 h1.52
  text "89" at 87.078,7.08 h1.52
  text "8.00mil (0.203mm)" at 95.51,7.08 h1.52
  text "PTH" at 111.679,7.08 h1.52
  text "Round" at 118.261,7.08 h1.52
  text "Top Layer - Bottom Layer" at 127.79,7.08 h1.52
  text "73" at 87.078,3.922 h1.52
  text "9.84mil (0.250mm)" at 95.51,3.922 h1.52
  text "PTH" at 111.679,3.922 h1.52
  text "Round" at 118.261,3.922 h1.52
  text "Top Layer - Bottom Layer" at 127.79,3.922 h1.52
  text "4" at 87.078,0.765 h1.52
  text "12.00mil (0.305mm)" at 95.51,0.765 h1.52
  text "PTH" at 111.679,0.765 h1.52
  text "Round" at 118.261,0.765 h1.52
  text "Top Layer - Bottom Layer" at 127.79,0.765 h1.52
  text "10" at 87.078,-2.393 h1.52
  text "12.60mil (0.320mm)" at 95.51,-2.393 h1.52
  text "PTH" at 111.679,-2.393 h1.52
  text "Round" at 118.261,-2.393 h1.52
  text "Top Layer - Bottom Layer" at 127.79,-2.393 h1.52
  text "C" at 78.801,-2.647 h1.4
  text "6" at 87.078,-5.551 h1.52
  text "23.62mil (0.600mm)" at 95.51,-5.551 h1.52
  text "PTH" at 111.679,-5.551 h1.52
  text "Round" at 118.261,-5.551 h1.52
  text "Top Layer - Bottom Layer" at 127.79,-5.551 h1.52
  text "2" at 87.078,-8.709 h1.52
  text "30.00mil (0.762mm)" at 95.51,-8.709 h1.52
  text "PTH" at 111.679,-8.709 h1.52
  text "Round" at 118.261,-8.709 h1.52
  text "Top Layer - Bottom Layer" at 127.79,-8.709 h1.52
  text "B" at 78.801,-8.962 h1.4
  text "4" at 87.078,-11.866 h1.52
  text "31.50mil (0.800mm)" at 95.51,-11.866 h1.52
  text "PTH" at 111.679,-11.866 h1.52
  text "Round" at 118.261,-11.866 h1.52
  text "Top Layer - Bottom Layer" at 127.79,-11.866 h1.52
  text "1" at 87.078,-15.024 h1.52
  text "19.69mil (0.500mm)" at 95.51,-15.024 h1.52
  text "NPTH" at 111.679,-15.024 h1.52
  text "Slot" at 118.261,-15.024 h1.52
  text "Top Layer - Bottom Layer" at 127.79,-15.024 h1.52
  text "+/-1.18mil" at 149.314,-15.024 h1.52
  text "2" at 87.078,-18.182 h1.52
  text "23.62mil (0.600mm)" at 95.51,-18.182 h1.52
  text "PTH" at 111.679,-18.182 h1.52
  text "Slot" at 118.261,-18.182 h1.52
  text "Top Layer - Bottom Layer" at 127.79,-18.182 h1.52
  text "+/-1.97mil" at 149.314,-18.182 h1.52
  text "2" at 87.078,-21.34 h1.52
  text "27.56mil (0.700mm)" at 95.51,-21.34 h1.52
  text "PTH" at 111.679,-21.34 h1.52
  text "Slot" at 118.261,-21.34 h1.52
  text "Top Layer - Bottom Layer" at 127.79,-21.34 h1.52
  text "+/-1.97mil" at 149.314,-21.34 h1.52
  text "2" at 87.078,-24.497 h1.52
  text "27.56mil (0.700mm)" at 95.51,-24.497 h1.52
  text "PTH" at 111.679,-24.497 h1.52
  text "Slot" at 118.261,-24.497 h1.52
  text "Top Layer - Bottom Layer" at 127.79,-24.497 h1.52
  text "+/-1.97mil" at 149.314,-24.497 h1.52
  text "4" at 87.078,-27.655 h1.52
  text "11.81mil (0.300mm)" at 95.51,-27.655 h1.52
  text "PTH" at 111.679,-27.655 h1.52
  text "Round" at 118.261,-27.655 h1.52
  text "Signal Layer 1 - Signal Layer 4" at 127.79,-27.655 h1.52
  text "A" at 78.801,-27.909 h1.4
  text "2" at 87.078,-30.813 h1.52
  text "13.78mil (0.350mm)" at 95.51,-30.813 h1.52
  text "PTH" at 111.679,-30.813 h1.52
  text "Round" at 118.261,-30.813 h1.52
  text "Signal Layer 2 - Signal Layer 3" at 127.79,-30.813 h1.52
  text "270 Total" at 87.078,-33.97 h1.52
  text "Slot definitions :" at 79.443,-36.181 h1.52
  text "Routed Path Length" at 90.891,-36.181 h1.52
  text "= Calculated from tool start centre position to tool end centre position." at 104.601,-36.181 h1.52
  text "Hole Length" at 90.891,-37.444 h1.52
  text "= Routed Path Length + Tool Size = Slot length as defined in the PCB layout" at 99.526,-37.444 h1.52
  text ".Layer_Name" at -61.462,-177.942 h1.52
M17 Embedded Cavity:
  text ".Layer_Name" at -61.462,-177.942 h1.52
M18 Embedded Assembly:
  text ".Layer_Name" at -61.462,-177.942 h1.52
M19 Embedded Keepout:
  text ".Layer_Name" at -61.462,-177.942 h1.52
Top 3D Body:
  lines w0.127: -9.02,8.74 -9.02,-8.81 8.98,-8.81 8.98,-8.19 8.98,9.94 -9.02,9.94 -9.02,8.75

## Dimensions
24.35,12.554 to 24.35,-26.45 on M2 Board Dimensions
-26.1,12.95 to 24.34,12.81 on M2 Board Dimensions
-76.118,-166.296 to -50.718,-166.296 on M2 Board Dimensions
